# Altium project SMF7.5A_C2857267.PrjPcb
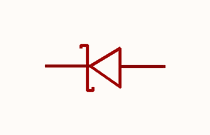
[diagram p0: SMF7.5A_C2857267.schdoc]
1 sheet, 1 parts. Net scope: global (net labels, ports and power ports of the same name join across sheets).

## Sheet SMF7.5A_C2857267.schdoc
size 127 x 101 mm

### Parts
D?  smf7.5a_c2857267  [SOD-123F_L2.8-W1.8-LS3.7-RD]  (value not drawn)

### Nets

Not connected (* = marked no-connect by the designer): D? 1(K) 2(A)

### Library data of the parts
D? = smf7.5a_c2857267: 极性:单向;反向截止电压(Vrwm):7.5V;钳位电压:12.9V;峰值脉冲电流(Ipp):15.5A;峰值脉冲功率(Ppp):200W;击穿电压(VBR):8.3V;; Manufacturer: JSMSEMI(杰盛微); AddInBom: yes; ModelId: 321bc188a2eb4b418ce08d06d1c3a1f1; ModelName: SOD-123FL_L2.8-W1.8-LS3.7-RD-1; ModelTransform: 145.669,70.866,0,0,0,0,0,0.276,0; Polarity: 单向; Reverse Stand-Off Voltage (Vrwm): 7.5V; Clamping Voltage: 12.9V; Peak Pulse Current (Ipp): 15.5A; Peak Pulse Power Dissipation (Ppp): 200W; Voltage - Breakdown: 8.3V; Reverse Leakage Current (Ir): 50uA; Number of Channels: 单路; Type: TVS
